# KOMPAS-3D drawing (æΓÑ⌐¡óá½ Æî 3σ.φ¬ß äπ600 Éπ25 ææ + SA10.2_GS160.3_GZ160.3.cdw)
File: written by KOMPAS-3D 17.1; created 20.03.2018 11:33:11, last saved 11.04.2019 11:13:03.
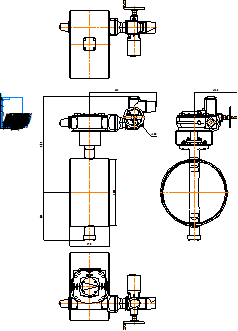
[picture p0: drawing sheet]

Sheet 1: A4, portrait

Title block, sheet 1: name: Стейнвал ТМ 3х.экс / Ду600 Ру25 СС + SA10.2_GS160.3_GZ160.3; material: Внимание! Данный продукт является объектом авторского права ООО «Торговый Дом АДЛ». / Запрещается изменение, копирование, распространение / (в том числе путем копирования на другие сайты и ресурсы в Интернете) / или любое иное использование информации и объектов без предварительного / согласия правообладателя (ООО «Торговый Дом АДЛ»).; mass: 97,3; sheets: 1; organisation: ООО "Торговый дом АДЛ"; sheet format: A4; stored path: \\adlc.lan\data\АДЛ_ПКД\3D-модели\ADL production\Дисковые поворотные затворы СТЕЙНВАЛ\Трехэксцентриковый\Стейнвал c-c\С эл.приводом\KOMPAS 2D\Стейнвал ТМ 3х.экс Ду600 Ру25 СС + SA10.2_GS160.3_GZ160.3.cdw

Views: Проекционный вид 2, Проекционный вид 3, Проекционный вид 4
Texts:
  kka
  adl
Dimensions and other numbers on the sheet: 413,8; 1:1; 1; 97,3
